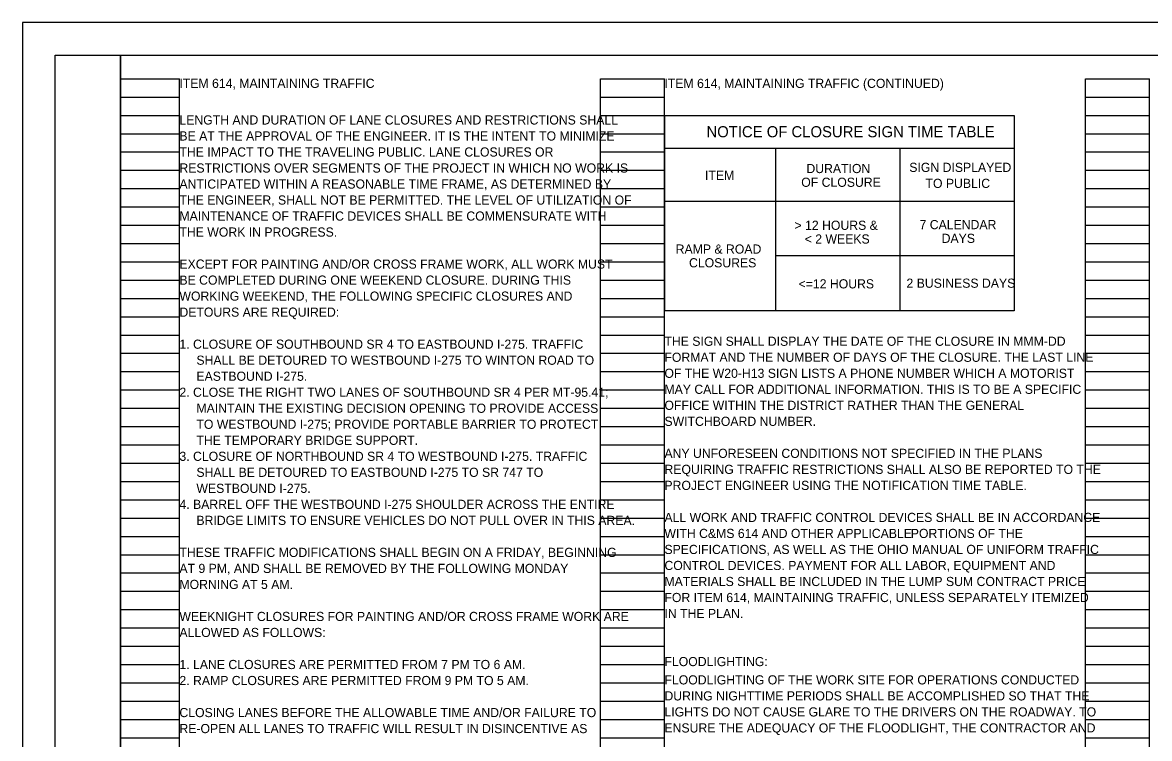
# Model space of a CAD drawing. Extents: x -11.6 to 64.7, y 0 to 22.
# Drawn here: x 0 to 17.24, y 11.05 to 22 of the extents above; entities that cross this region are included whole.
import ezdxf

# ---------------------------------------------------------------- set-up
doc = ezdxf.new("R2010")
doc.units = 0
for name, color, linetype in [('BR_P_Gen_Text', 7, 'Continuous'), ('SH_Border', 7, 'Continuous'), ('SH_Cut_Line', 7, 'Continuous'), ('SH_Data', 7, 'Continuous'), ('SH_Text', 7, 'Continuous')]:
    doc.layers.add(name, color=color, linetype=linetype)

msp = doc.modelspace()

# ---------------------------------------------------------------- linework, layer by layer
at = {"layer": 'BR_P_Gen_Text'}
for p, q in [((9.82, 20.58), (9.82, 17.591)), ((9.82, 20.58), (15.169, 20.58)), ((15.169, 20.58), (15.169, 17.591)), ((9.82, 20.08), (15.169, 20.08)), ((11.52, 20.08), (11.52, 17.591)), ((13.42, 20.08), (13.42, 17.591)), ((9.82, 19.269), (15.169, 19.269)), ((15.169, 18.43), (11.52, 18.43)), ((15.169, 17.591), (9.82, 17.591))]:
    msp.add_line(p, q, dxfattribs=at)
at = {"layer": 'SH_Border'}
for points in [[(0.5, 21.5), (1.5, 21.5), (1.5, 0.5), (0.5, 0.5)], [(1.5, 21.5), (33.5, 21.5), (33.5, 0.5), (1.5, 0.5)]]:
    msp.add_lwpolyline(points, close=True, dxfattribs=at)
at = {"layer": 'SH_Cut_Line'}
msp.add_lwpolyline([(0, 0), (34, 0), (34, 22), (0, 22)], close=True, dxfattribs=at)
at = {"layer": 'SH_Data'}
for p, q in [((1.5, 0.98), (1.5, 21.14)), ((1.5, 21.14), (2.4, 21.14)), ((2.4, 0.98), (2.4, 21.14)), ((8.84, 0.98), (8.84, 21.14)), ((8.84, 21.14), (9.82, 21.14)), ((9.82, 0.98), (9.82, 21.14)), ((16.26, 0.98), (16.26, 21.14)), ((16.26, 21.14), (17.24, 21.14)), ((17.24, 0.98), (17.24, 21.14)), ((1.5, 20.86), (2.4, 20.86)), ((8.84, 20.86), (9.82, 20.86)), ((16.26, 20.86), (17.24, 20.86)), ((1.5, 20.58), (2.4, 20.58)), ((8.84, 20.58), (9.82, 20.58)), ((16.26, 20.58), (17.24, 20.58)), ((1.5, 20.3), (2.4, 20.3)), ((8.84, 20.3), (9.82, 20.3)), ((16.26, 20.3), (17.24, 20.3)), ((1.5, 20.02), (2.4, 20.02)), ((8.84, 20.02), (9.82, 20.02)), ((16.26, 20.02), (17.24, 20.02)), ((1.5, 19.74), (2.4, 19.74)), ((8.84, 19.74), (9.82, 19.74)), ((16.26, 19.74), (17.24, 19.74)), ((1.5, 19.46), (2.4, 19.46)), ((8.84, 19.46), (9.82, 19.46)), ((16.26, 19.46), (17.24, 19.46)), ((1.5, 19.18), (2.4, 19.18)), ((8.84, 19.18), (9.82, 19.18)), ((16.26, 19.18), (17.24, 19.18)), ((1.5, 18.9), (2.4, 18.9)), ((8.84, 18.9), (9.82, 18.9)), ((16.26, 18.9), (17.24, 18.9)), ((1.5, 18.62), (2.4, 18.62)), ((8.84, 18.62), (9.82, 18.62)), ((16.26, 18.62), (17.24, 18.62)), ((1.5, 18.34), (2.4, 18.34)), ((8.84, 18.34), (9.82, 18.34)), ((16.26, 18.34), (17.24, 18.34)), ((1.5, 18.06), (2.4, 18.06)), ((8.84, 18.06), (9.82, 18.06)), ((16.26, 18.06), (17.24, 18.06)), ((1.5, 17.78), (2.4, 17.78)), ((8.84, 17.78), (9.82, 17.78)), ((16.26, 17.78), (17.24, 17.78)), ((1.5, 17.5), (2.4, 17.5)), ((8.84, 17.5), (9.82, 17.5)), ((16.26, 17.5), (17.24, 17.5)), ((1.5, 17.22), (2.4, 17.22)), ((8.84, 17.22), (9.82, 17.22)), ((16.26, 17.22), (17.24, 17.22)), ((1.5, 16.94), (2.4, 16.94)), ((8.84, 16.94), (9.82, 16.94)), ((16.26, 16.94), (17.24, 16.94)), ((1.5, 16.66), (2.4, 16.66)), ((8.84, 16.66), (9.82, 16.66)), ((16.26, 16.66), (17.24, 16.66)), ((1.5, 16.38), (2.4, 16.38)), ((8.84, 16.38), (9.82, 16.38)), ((16.26, 16.38), (17.24, 16.38)), ((1.5, 16.1), (2.4, 16.1)), ((8.84, 16.1), (9.82, 16.1)), ((16.26, 16.1), (17.24, 16.1)), ((1.5, 15.82), (2.4, 15.82)), ((8.84, 15.82), (9.82, 15.82)), ((16.26, 15.82), (17.24, 15.82)), ((1.5, 15.54), (2.4, 15.54)), ((8.84, 15.54), (9.82, 15.54)), ((16.26, 15.54), (17.24, 15.54)), ((1.5, 15.26), (2.4, 15.26)), ((8.84, 15.26), (9.82, 15.26)), ((16.26, 15.26), (17.24, 15.26)), ((1.5, 14.98), (2.4, 14.98)), ((8.84, 14.98), (9.82, 14.98)), ((16.26, 14.98), (17.24, 14.98)), ((1.5, 14.7), (2.4, 14.7)), ((8.84, 14.7), (9.82, 14.7)), ((16.26, 14.7), (17.24, 14.7)), ((1.5, 14.42), (2.4, 14.42)), ((8.84, 14.42), (9.82, 14.42)), ((16.26, 14.42), (17.24, 14.42)), ((1.5, 14.14), (2.4, 14.14)), ((8.84, 14.14), (9.82, 14.14)), ((16.26, 14.14), (17.24, 14.14)), ((1.5, 13.86), (2.4, 13.86)), ((8.84, 13.86), (9.82, 13.86)), ((16.26, 13.86), (17.24, 13.86)), ((1.5, 13.58), (2.4, 13.58)), ((8.84, 13.58), (9.82, 13.58)), ((16.26, 13.58), (17.24, 13.58)), ((1.5, 13.3), (2.4, 13.3)), ((8.84, 13.3), (9.82, 13.3)), ((16.26, 13.3), (17.24, 13.3)), ((1.5, 13.02), (2.4, 13.02)), ((8.84, 13.02), (9.82, 13.02)), ((16.26, 13.02), (17.24, 13.02)), ((1.5, 12.74), (2.4, 12.74)), ((8.84, 12.74), (9.82, 12.74)), ((16.26, 12.74), (17.24, 12.74)), ((1.5, 12.46), (2.4, 12.46)), ((8.84, 12.46), (9.82, 12.46)), ((16.26, 12.46), (17.24, 12.46)), ((1.5, 12.18), (2.4, 12.18)), ((8.84, 12.18), (9.82, 12.18)), ((16.26, 12.18), (17.24, 12.18)), ((1.5, 11.9), (2.4, 11.9)), ((8.84, 11.9), (9.82, 11.9)), ((16.26, 11.9), (17.24, 11.9)), ((1.5, 11.62), (2.4, 11.62)), ((8.84, 11.62), (9.82, 11.62)), ((16.26, 11.62), (17.24, 11.62)), ((1.5, 11.34), (2.4, 11.34)), ((8.84, 11.34), (9.82, 11.34)), ((16.26, 11.34), (17.24, 11.34)), ((1.5, 11.06), (2.4, 11.06)), ((8.84, 11.06), (9.82, 11.06)), ((16.26, 11.06), (17.24, 11.06))]:
    msp.add_line(p, q, dxfattribs=at)

# ---------------------------------------------------------------- texts
at = {"layer": 'BR_P_Gen_Text'}
for s, height, p in [('NOTICE OF CLOSURE SIGN TIME TABLE', 0.17, (10.463, 20.245)), ('DURATION ', 0.14, (11.992, 19.697)), ('SIGN DISPLAYED', 0.14, (13.566, 19.715)), ('ITEM', 0.14, (10.441, 19.592)), ('OF CLOSURE', 0.14, (11.913, 19.487)), ('TO PUBLIC', 0.14, (13.814, 19.47)), ('> 12 HOURS &', 0.14, (11.81, 18.829)), ('7 CALENDAR', 0.14, (13.723, 18.839)), ('< 2 WEEKS', 0.14, (11.966, 18.619)), ('DAYS', 0.14, (14.061, 18.629)), ('RAMP & ROAD', 0.14, (9.992, 18.465)), ('CLOSURES', 0.14, (10.196, 18.255)), ('<=12 HOURS', 0.14, (11.872, 17.933)), ('2 BUSINESS DAYS', 0.14, (13.523, 17.943))]:
    msp.add_text(s, height=height, dxfattribs=at).set_placement(p)
at = {"layer": 'SH_Text'}
for s, p in [('ITEM 614, MAINTAINING TRAFFIC', (2.4, 21)), ('ITEM 614, MAINTAINING TRAFFIC (CONTINUED)', (9.82, 21)), ('LENGTH AND DURATION OF LANE CLOSURES AND RESTRICTIONS SHALL ', (2.4, 20.44)), ('BE AT THE APPROVAL OF THE ENGINEER. IT IS THE INTENT TO MINIMIZE ', (2.4, 20.195)), ('THE IMPACT TO THE TRAVELING PUBLIC. LANE CLOSURES OR ', (2.4, 19.95)), ('RESTRICTIONS OVER SEGMENTS OF THE PROJECT IN WHICH NO WORK IS ', (2.4, 19.705)), ('ANTICIPATED WITHIN A REASONABLE TIME FRAME, AS DETERMINED BY ', (2.4, 19.46)), ('THE ENGINEER, SHALL NOT BE PERMITTED. THE LEVEL OF UTILIZATION OF', (2.4, 19.215)), ('MAINTENANCE OF TRAFFIC DEVICES SHALL BE COMMENSURATE WITH ', (2.4, 18.97)), ('THE WORK IN PROGRESS.', (2.4, 18.725)), ('EXCEPT FOR PAINTING AND/OR CROSS FRAME WORK, ALL WORK MUST ', (2.4, 18.235)), ('BE COMPLETED DURING ONE WEEKEND CLOSURE. DURING THIS ', (2.4, 17.99)), ('WORKING WEEKEND, THE FOLLOWING SPECIFIC CLOSURES AND ', (2.4, 17.745)), ('DETOURS ARE REQUIRED:', (2.4, 17.5)), ('1. CLOSURE OF SOUTHBOUND SR 4 TO EASTBOUND I-275. TRAFFIC ', (2.4, 17.01)), ('THE SIGN SHALL DISPLAY THE DATE OF THE CLOSURE IN MMM-DD', (9.82, 17.055)), ('     SHALL BE DETOURED TO WESTBOUND I-275 TO WINTON ROAD TO ', (2.4, 16.765)), ('FORMAT AND THE NUMBER OF DAYS OF THE CLOSURE. THE LAST LINE ', (9.82, 16.81)), ('     EASTBOUND I-275.', (2.4, 16.52)), ('OF THE W20-H13 SIGN LISTS A PHONE NUMBER WHICH A MOTORIST ', (9.82, 16.565)), ('2. CLOSE THE RIGHT TWO LANES OF SOUTHBOUND SR 4 PER MT-95.41;', (2.4, 16.275)), ('MAY CALL FOR ADDITIONAL INFORMATION. THIS IS TO BE A SPECIFIC ', (9.82, 16.32)), ('OFFICE WITHIN THE DISTRICT RATHER THAN THE GENERAL ', (9.82, 16.075)), ('     MAINTAIN THE EXISTING DECISION OPENING TO PROVIDE ACCESS', (2.4, 16.03)), ('     TO WESTBOUND I-275; PROVIDE PORTABLE BARRIER TO PROTECT', (2.4, 15.785)), ('SWITCHBOARD NUMBER.', (9.82, 15.83)), ('     THE TEMPORARY BRIDGE SUPPORT.', (2.4, 15.54)), ('3. CLOSURE OF NORTHBOUND SR 4 TO WESTBOUND I-275. TRAFFIC', (2.4, 15.295)), ('ANY UNFORESEEN CONDITIONS NOT SPECIFIED IN THE PLANS ', (9.82, 15.34)), ('     SHALL BE DETOURED TO EASTBOUND I-275 TO SR 747 TO', (2.4, 15.05)), ('REQUIRING TRAFFIC RESTRICTIONS SHALL ALSO BE REPORTED TO THE', (9.82, 15.095)), ('     WESTBOUND I-275.', (2.4, 14.805)), ('PROJECT ENGINEER USING THE NOTIFICATION TIME TABLE.', (9.82, 14.85)), ('4. BARREL OFF THE WESTBOUND I-275 SHOULDER ACROSS THE ENTIRE ', (2.4, 14.56)), ('ALL WORK AND TRAFFIC CONTROL DEVICES SHALL BE IN ACCORDANCE ', (9.82, 14.36)), ('     BRIDGE LIMITS TO ENSURE VEHICLES DO NOT PULL OVER IN THIS AREA.', (2.4, 14.315)), ('WITH C&MS 614 AND OTHER APPLICABLE ', (9.82, 14.115)), ('PORTIONS OF THE ', (13.589, 14.115)), ('THESE TRAFFIC MODIFICATIONS SHALL BEGIN ON A FRIDAY, BEGINNING', (2.4, 13.825)), ('SPECIFICATIONS, AS WELL AS THE OHIO MANUAL OF UNIFORM TRAFFIC ', (9.82, 13.87)), ('AT 9 PM, AND SHALL BE REMOVED BY THE FOLLOWING MONDAY', (2.4, 13.58)), ('CONTROL DEVICES. PAYMENT FOR ALL LABOR, EQUIPMENT AND ', (9.82, 13.625)), ('MORNING AT 5 AM.', (2.4, 13.335)), ('MATERIALS SHALL BE INCLUDED IN THE LUMP SUM CONTRACT PRICE ', (9.82, 13.38)), ('FOR ITEM 614, MAINTAINING TRAFFIC, UNLESS SEPARATELY ITEMIZED ', (9.82, 13.135)), ('WEEKNIGHT CLOSURES FOR PAINTING AND/OR CROSS FRAME WORK ARE ', (2.4, 12.845)), ('IN THE PLAN.', (9.82, 12.89)), ('ALLOWED AS FOLLOWS:', (2.4, 12.6)), ('1. LANE CLOSURES ARE PERMITTED FROM 7 PM TO 6 AM.', (2.4, 12.11)), ('FLOODLIGHTING:', (9.82, 12.155)), ('2. RAMP CLOSURES ARE PERMITTED FROM 9 PM TO 5 AM.', (2.4, 11.865)), ('FLOODLIGHTING OF THE WORK SITE FOR OPERATIONS CONDUCTED ', (9.82, 11.875)), ('DURING NIGHTTIME PERIODS SHALL BE ACCOMPLISHED SO THAT THE', (9.82, 11.63)), ('CLOSING LANES BEFORE THE ALLOWABLE TIME AND/OR FAILURE TO', (2.4, 11.375)), ('LIGHTS DO NOT CAUSE GLARE TO THE DRIVERS ON THE ROADWAY. TO', (9.82, 11.385)), ('RE-OPEN ALL LANES TO TRAFFIC WILL RESULT IN DISINCENTIVE AS', (2.4, 11.13)), ('ENSURE THE ADEQUACY OF THE FLOODLIGHT, THE CONTRACTOR AND', (9.82, 11.14))]:
    msp.add_text(s, height=0.14, dxfattribs=at).set_placement(p)

doc.saveas('drawing.dxf')
